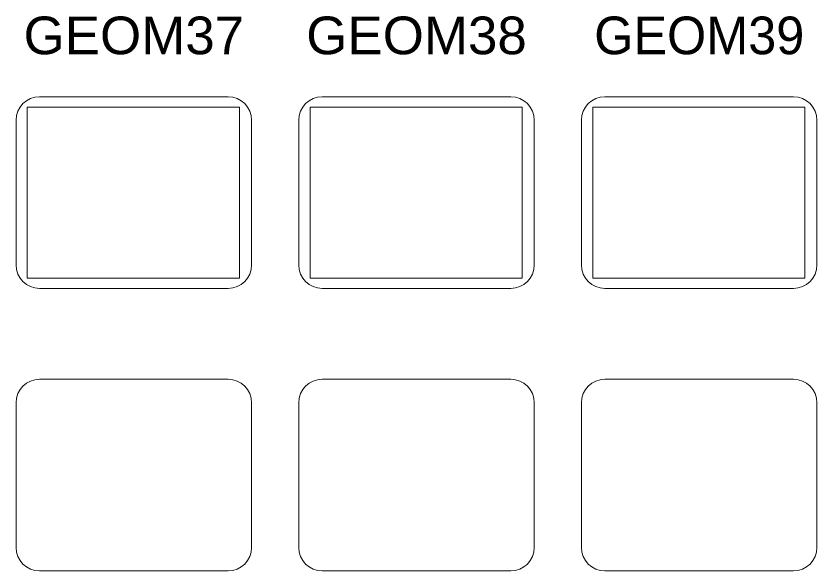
# Model space of a CAD drawing. Extents: x 95935 to 95946.4, y 95971.2 to 95974.7.
# Drawn here: x 95936.886 to 95938.586, y 95971.925 to 95973.103 of the extents above; entities that cross this region are included whole.
import ezdxf
from ezdxf.enums import TextEntityAlignment as Align

# ---------------------------------------------------------------- set-up
doc = ezdxf.new("R2010")
doc.units = 0
doc.header["$LTSCALE"] = 0.032
doc.layers.add('1', color=7, linetype='Continuous', lineweight=13)
doc.layers.add('2', color=7, linetype='Continuous', lineweight=13)
doc.layers.add('20', color=7, linetype='Continuous')

msp = doc.modelspace()

# ---------------------------------------------------------------- linework, layer by layer
at = {"layer": '1'}
for p, q in [((95936.9357, 95972.9318), (95937.3357, 95972.9318)), ((95937.5357, 95972.9318), (95937.9357, 95972.9318)), ((95938.1357, 95972.9318), (95938.5357, 95972.9318)), ((95936.8857, 95972.5747), (95936.8857, 95972.8818)), ((95937.3857, 95972.8818), (95937.3857, 95972.5747)), ((95937.4857, 95972.5747), (95937.4857, 95972.8818)), ((95937.9857, 95972.8818), (95937.9857, 95972.5747)), ((95938.0857, 95972.5747), (95938.0857, 95972.8818)), ((95938.5857, 95972.8818), (95938.5857, 95972.5747)), ((95937.3357, 95972.5247), (95936.9357, 95972.5247)), ((95937.9357, 95972.5247), (95937.5357, 95972.5247)), ((95938.5357, 95972.5247), (95938.1357, 95972.5247)), ((95936.9357, 95972.3318), (95937.3357, 95972.3318)), ((95937.5357, 95972.3318), (95937.9357, 95972.3318)), ((95938.1357, 95972.3318), (95938.5357, 95972.3318)), ((95936.8857, 95971.9747), (95936.8857, 95972.2818)), ((95937.3857, 95972.2818), (95937.3857, 95971.9747)), ((95937.4857, 95971.9747), (95937.4857, 95972.2818)), ((95937.9857, 95972.2818), (95937.9857, 95971.9747)), ((95938.0857, 95971.9747), (95938.0857, 95972.2818)), ((95938.5857, 95972.2818), (95938.5857, 95971.9747)), ((95937.3357, 95971.9247), (95936.9357, 95971.9247)), ((95937.9357, 95971.9247), (95937.5357, 95971.9247)), ((95938.5357, 95971.9247), (95938.1357, 95971.9247))]:
    msp.add_line(p, q, dxfattribs=at)
for centre, start, end in [((95936.9357, 95972.8818), 90, 180), ((95937.3357, 95972.8818), 0, 90), ((95937.5357, 95972.8818), 90, 180), ((95937.9357, 95972.8818), 0, 90), ((95938.1357, 95972.8818), 90, 180), ((95938.5357, 95972.8818), 0, 90), ((95936.9357, 95972.5747), 180, 270), ((95937.3357, 95972.5747), 270, 0), ((95937.5357, 95972.5747), 180, 270), ((95937.9357, 95972.5747), 270, 0), ((95938.1357, 95972.5747), 180, 270), ((95938.5357, 95972.5747), 270, 0), ((95936.9357, 95972.2818), 90, 180), ((95937.3357, 95972.2818), 0, 90), ((95937.5357, 95972.2818), 90, 180), ((95937.9357, 95972.2818), 0, 90), ((95938.1357, 95972.2818), 90, 180), ((95938.5357, 95972.2818), 0, 90), ((95936.9357, 95971.9747), 180, 270), ((95937.3357, 95971.9747), 270, 0), ((95937.5357, 95971.9747), 180, 270), ((95937.9357, 95971.9747), 270, 0), ((95938.1357, 95971.9747), 180, 270), ((95938.5357, 95971.9747), 270, 0)]:
    msp.add_arc(centre, 0.05, start, end, dxfattribs=at)
at = {"layer": '2'}
for points in [[(95937.3601, 95972.9099), (95936.9097, 95972.9099), (95936.9097, 95972.5468), (95937.3601, 95972.5468)], [(95937.9601, 95972.9099), (95937.5097, 95972.9099), (95937.5097, 95972.5468), (95937.9601, 95972.5468)], [(95938.5601, 95972.9099), (95938.1097, 95972.9099), (95938.1097, 95972.5468), (95938.5601, 95972.5468)]]:
    msp.add_lwpolyline(points, close=True, dxfattribs=at)

# ---------------------------------------------------------------- texts
at = {"layer": '20', "width": 1.05}
for s, p in [('GEOM37', (95937.1358, 95973.022)), ('GEOM38', (95937.7358, 95973.022))]:
    msp.add_text(s, height=0.08, dxfattribs=at).set_placement(p, align=Align.CENTER)
at = {"layer": '20'}
msp.add_text('GEOM39', height=0.08, dxfattribs=at).set_placement((95938.3358, 95973.022), align=Align.CENTER)

doc.saveas('drawing.dxf')
